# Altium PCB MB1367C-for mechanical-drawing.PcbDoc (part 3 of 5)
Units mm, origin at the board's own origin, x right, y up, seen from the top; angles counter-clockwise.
Board outline 70 x 82.5 mm, 4 copper layers (Top Layer, Signal Layer 1, Signal Layer 2, Bottom Layer), stack 1.614 mm thick; 191 components, 143 nets, 808 pads, 920 vias.
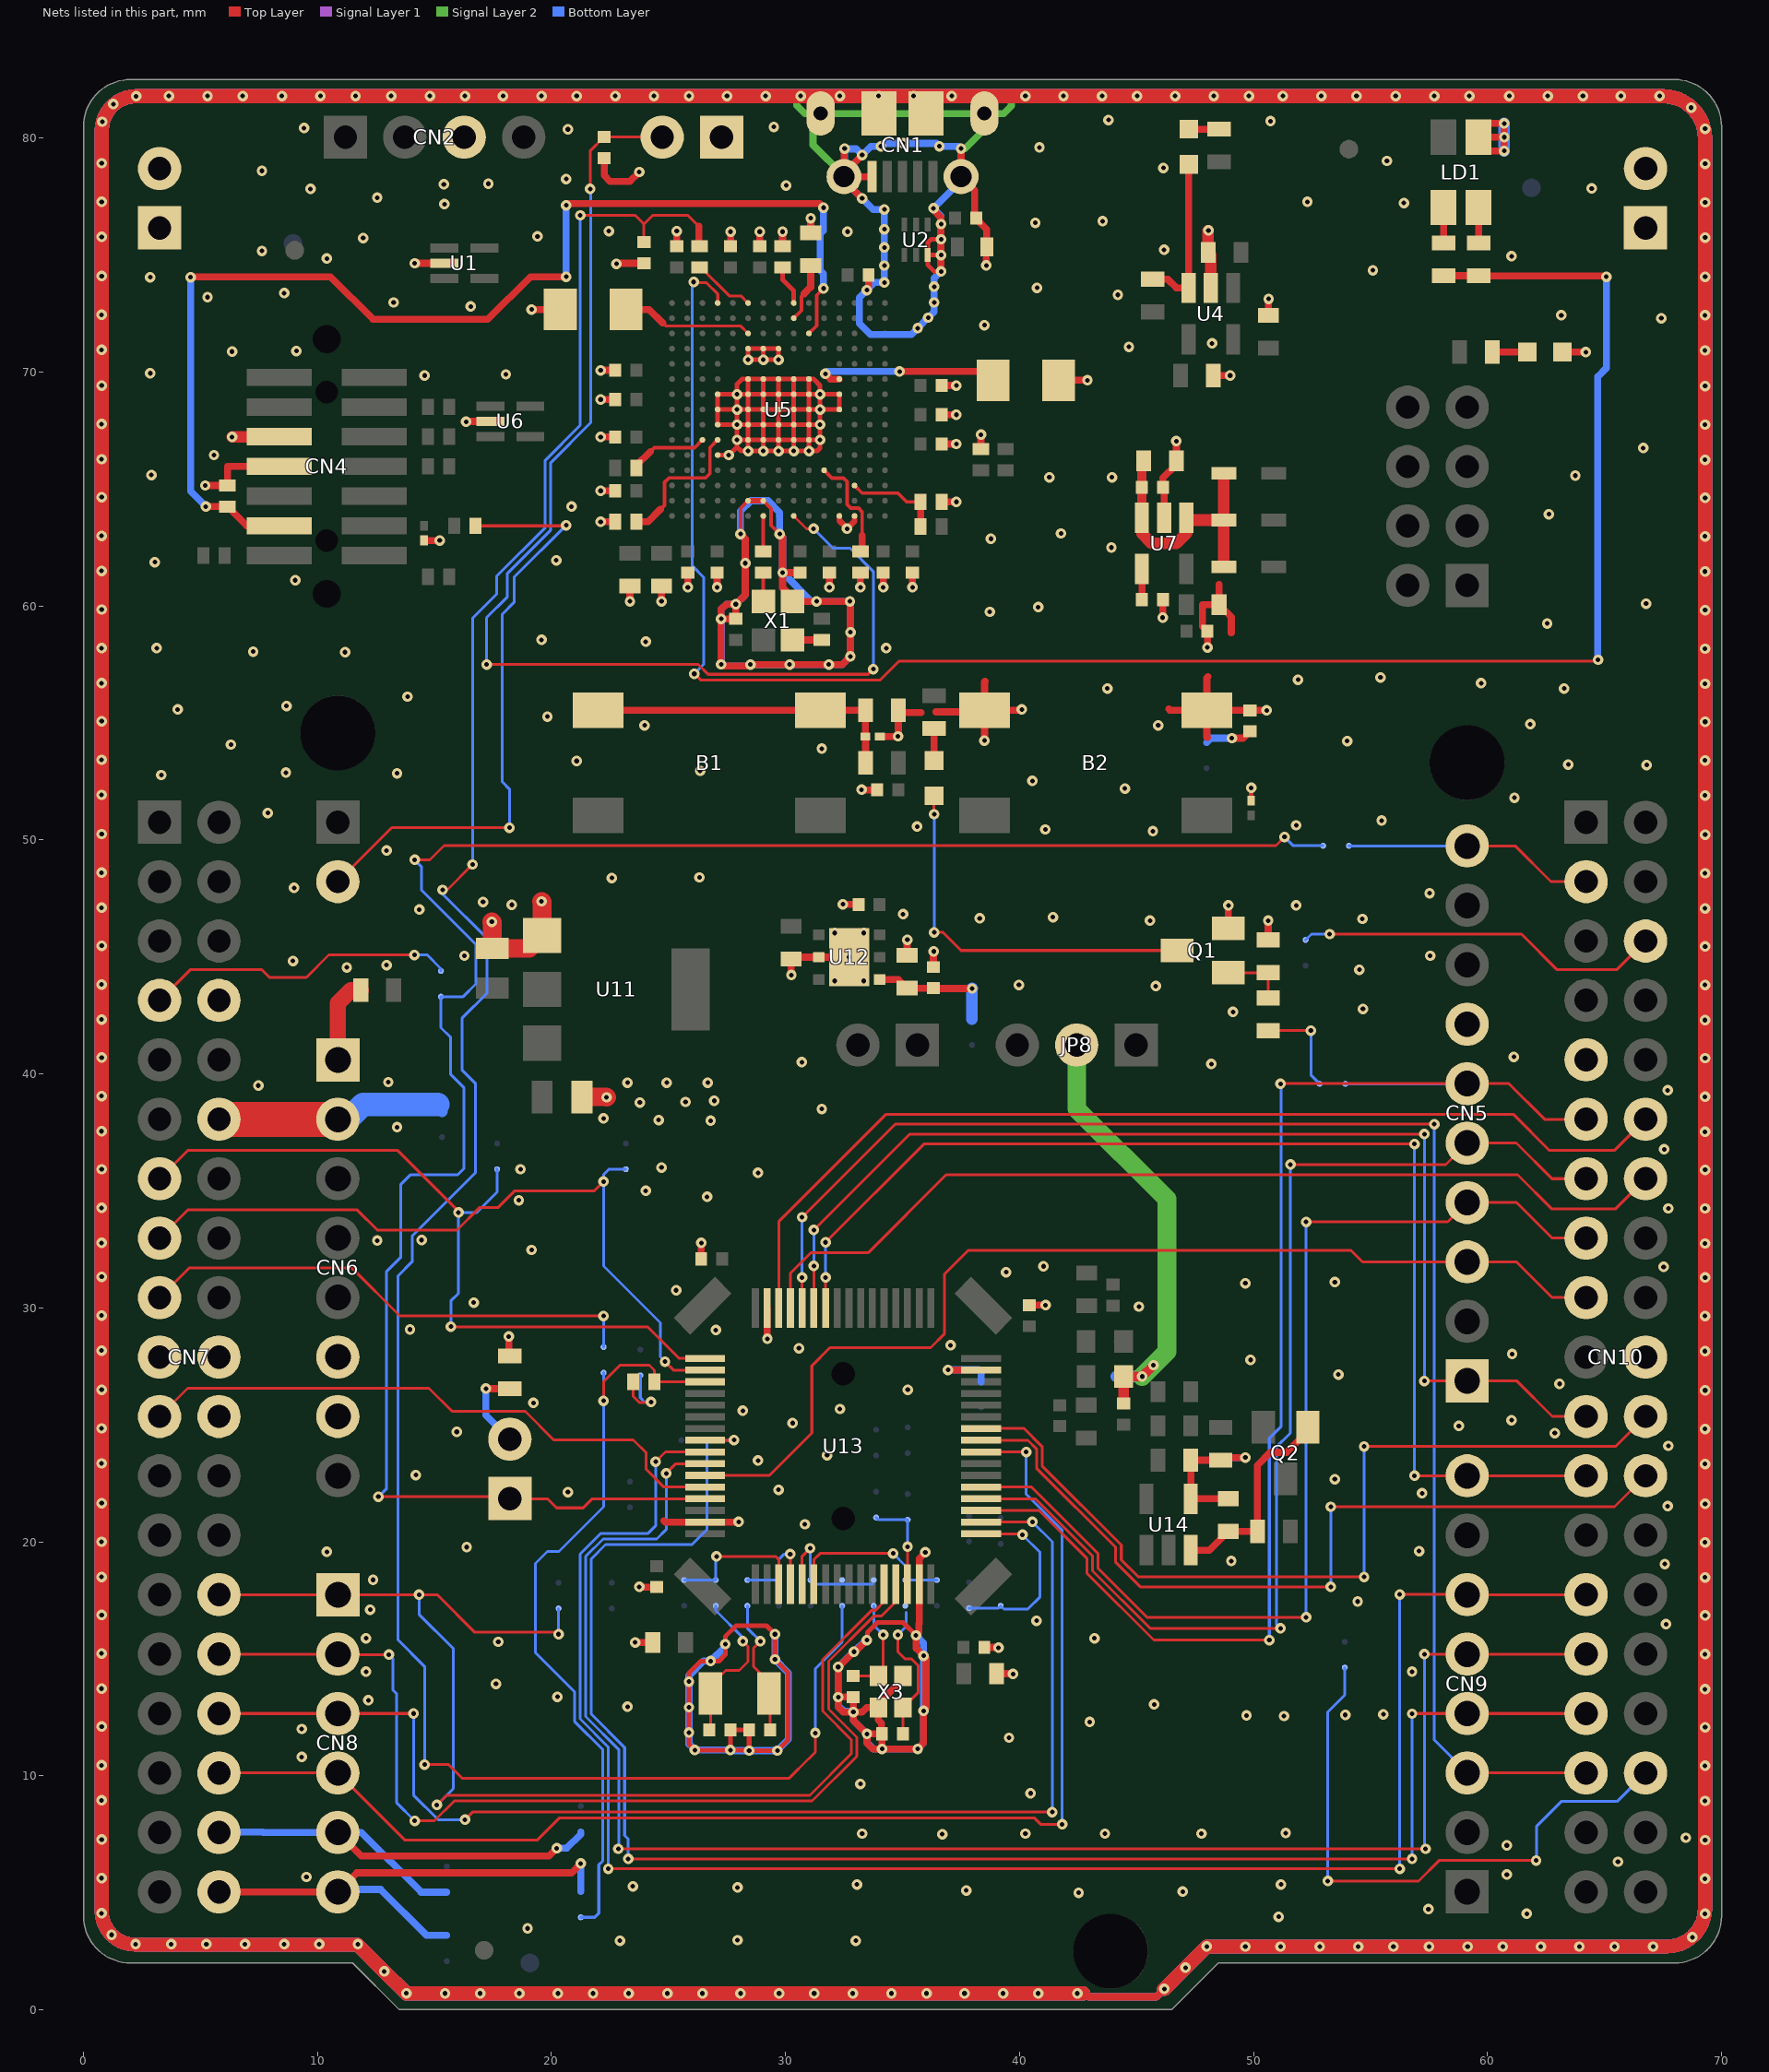
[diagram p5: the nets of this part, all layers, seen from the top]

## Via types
v1: diameter 0.45, hole 0.2, Top Layer to Bottom Layer, tented both sides, 920 vias

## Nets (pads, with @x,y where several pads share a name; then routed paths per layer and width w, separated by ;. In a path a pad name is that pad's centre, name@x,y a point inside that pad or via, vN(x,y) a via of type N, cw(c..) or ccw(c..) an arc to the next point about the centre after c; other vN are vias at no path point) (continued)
GND: B2.3 B2.4 C1.1 C2.1 C3.1 C4.1 C5.1 C6.1 C7.1 C8.1 C9.1 C10.1 C11.1 C12.1 C13.1 C14.1 C15.1 C16.1 C17.1 C18.1 C19.1 C20.1 C21.1 C22.1 C23.1 C24.1 C25.1 C26.1 C27.1 C28.1 C29.1 C30.1 C31.1 C32.1 C33.1 C34.1 C35.1 C36.1 C37.1 C38.1 C39.1 C40.1 C41.1 C42.1 C45.1 C52.1 C53.1 C54.1 C55.1 C56.1 C57.2 C58.2 C59.1 CN1.5 CN1.6 CN1.7 CN1.8 CN1.9 CN1.10 CN1.11 CN2.3 CN4.5 CN4.7 CN5.7 CN6.6 CN6.7 CN7.8 CN7.19 CN7.20 CN7.22 CN10.9 CN10.20 CN11.1 CN11.2 CN12.1 CN12.2 JP1.1 LD1.1 LD3.2 Q1.2 R5.1 R8.2 R11.1 R15.1 R16.2 R17.1 R21.1 R26.1 R28.1 R31.1 SB11.1 U1.2 U2.3 U3.2 U4.2 U5.D5 U5.D7 U5.D8 U5.D9 U5.F2 U5.F6 U5.F7 U5.F8 U5.F9 U5.F10 U5.F12 U5.G2 U5.G6 U5.G7 U5.G8 U5.G9 U5.G10 U5.G12 U5.H6 U5.H7 U5.H8 U5.H9 U5.H10 U5.H12 U5.J6 U5.J7 U5.J8 U5.J9 U5.J10 U5.K6 U5.K7 U5.K8 U5.K9 U5.K10 U5.M1 U5.M8 U5.M9 U5.N1 U6.2 U7.2 U8.2 U9.2 U10.2 U11.1 U12.2 U12.EP U13.15 U13.31 U13.47 U13.63 X1.2 X3.2 X3.4 | length 1507.3
  Top Layer w0.15: v1(28.075,63.075) 28.075,64.175 U5.F2@28.4,64.5 ; U5.G2@29.05,64.5 29.38,64.17 29.38,63.445 v1(29.75,63.075)
  Top Layer w0.2: U5.D5@27.1,66.45 v1(27.575,66.45) 27.925,66.8 ; v1(33.475,15.8) 33.5,15.825 33.5,16.125 33.93,16.555 35.02,16.555 v1(35.575,16) ; v1(36.65,74.3) 36.35,74.3 36.075,74.575 U2.3@36.075,75 ; v1@36.65,74.975 36.625,75 U2.3@36.075,75 ; v1(36.65,75.675) 36.225,75.675 36.075,75.525 U2.3@36.075,75 ; U10.2@49.895,51.677 49.895,52.22 v1(49.9,52.225) ; U5.D8@27.1,68.4 v1(27.925,68.4) ; U5.D8@27.1,68.4 U5.D7@27.1,67.75 v1(27.925,67.75) ; U5.D8@27.1,68.4 U5.D9@27.1,69.05 v1(27.925,69.05) ; v1(27.645,11.1) v1(26.125,11.1) 25.875,11.35 v1(25.875,11.85) v1(25.875,12.925) v1(25.875,14.025) 25.875,14.399 26.376,14.9 v1(26.8,14.9) 27.15,14.9 27.425,15.175 v1(27.425,15.625) 27.425,15.949 27.891,16.415 29.185,16.415 v1(29.55,16.05) v1(29.55,14.975) 30.105,14.42 30.105,11.53 v1(29.65,11.075) v1(28.445,11.075) ; v1(27.645,11.1) C57.2@27.645,11.965 C58.2@28.445,11.965 v1(28.445,11.075) ; v1(27.645,11.1) 28.42,11.1 v1(28.445,11.075) ; 27.925,66.8 v1(27.925,67.1) ; 27.925,66.8 28.1,66.625 v1(28.4,66.625) ; v1(27.925,67.1) U5.F6@28.4,67.1 ; v1(27.925,67.1) v1(27.925,67.75) ; v1(27.925,67.75) U5.F7@28.4,67.75 ; v1(27.925,67.75) v1(27.925,68.4) ; v1(27.925,68.4) U5.F8@28.4,68.4 ; v1(27.925,68.4) v1(27.925,69.05) ; v1(27.925,69.05) U5.F9@28.4,69.05 ; v1(27.925,69.05) 27.925,69.475 28.15,69.7 U5.F10@28.4,69.7 ; v1(28.4,66.625) U5.F6@28.4,67.1 ; v1(28.4,66.625) v1(29.05,66.625) ; U5.F6@28.4,67.1 U5.G6@29.05,67.1 ; U5.F6@28.4,67.1 U5.F7@28.4,67.75 ; U5.F7@28.4,67.75 U5.F8@28.4,68.4 ; U5.F7@28.4,67.75 U5.G7@29.05,67.75 ; U5.F8@28.4,68.4 U5.F9@28.4,69.05 ; U5.F8@28.4,68.4 U5.G8@29.05,68.4 ; U5.F9@28.4,69.05 U5.F10@28.4,69.7 ; U5.F9@28.4,69.05 U5.G9@29.05,69.05 ; U5.F10@28.4,69.7 U5.G10@29.05,69.7 ; v1(29.05,66.625) U5.G6@29.05,67.1 ; v1(29.05,66.625) v1(29.7,66.625) ; U5.G6@29.05,67.1 U5.H6@29.7,67.1 ; U5.G6@29.05,67.1 U5.G7@29.05,67.75 ; U5.G7@29.05,67.75 U5.G8@29.05,68.4 ; U5.G7@29.05,67.75 U5.H7@29.7,67.75 ; U5.G8@29.05,68.4 U5.G9@29.05,69.05 ; U5.G8@29.05,68.4 U5.H8@29.7,68.4 ; U5.G9@29.05,69.05 U5.G10@29.05,69.7 ; U5.G9@29.05,69.05 U5.H9@29.7,69.05 ; U5.G10@29.05,69.7 U5.H10@29.7,69.7 ; v1(29.05,70.525) U5.G12@29.05,71 ; v1(29.05,70.525) v1(29.7,70.525) U5.H12@29.7,71 U5.G12@29.05,71 ; v1(29.05,70.525) v1(28.4,70.525) U5.F12@28.4,71 U5.G12@29.05,71 ; v1(29.7,66.625) U5.H6@29.7,67.1 ; v1(29.7,66.625) v1(30.35,66.625) ; U5.H6@29.7,67.1 U5.J6@30.35,67.1 ; U5.H6@29.7,67.1 U5.H7@29.7,67.75 ; U5.H7@29.7,67.75 U5.H8@29.7,68.4 ; U5.H7@29.7,67.75 U5.J7@30.35,67.75 ; U5.H8@29.7,68.4 U5.H9@29.7,69.05 ; U5.H8@29.7,68.4 U5.J8@30.35,68.4 ; U5.H9@29.7,69.05 U5.H10@29.7,69.7 ; U5.H9@29.7,69.05 U5.J9@30.35,69.05 ; U5.H10@29.7,69.7 U5.J10@30.35,69.7 ; v1(30.35,66.625) U5.J6@30.35,67.1 ; v1(30.35,66.625) v1(31,66.625) ; U5.J6@30.35,67.1 U5.J7@30.35,67.75 ; U5.J6@30.35,67.1 U5.K6@31,67.1 ; U5.J7@30.35,67.75 U5.J8@30.35,68.4 ; U5.J7@30.35,67.75 U5.K7@31,67.75 ; U5.J8@30.35,68.4 U5.J9@30.35,69.05 ; U5.J8@30.35,68.4 U5.K8@31,68.4 ; U5.J9@30.35,69.05 U5.J10@30.35,69.7 ; U5.J9@30.35,69.05 U5.K9@31,69.05 ; U5.J10@30.35,69.7 U5.K10@31,69.7 ; v1(31,66.625) U5.K6@31,67.1 ; v1(31,66.625) 31.35,66.625 31.475,66.75 v1(31.475,67.1) ; U5.K6@31,67.1 v1(31.475,67.1) ; U5.K6@31,67.1 U5.K7@31,67.75 ; U5.K7@31,67.75 v1(31.475,67.75) ; U5.K7@31,67.75 U5.K8@31,68.4 ; U5.K8@31,68.4 U5.K9@31,69.05 ; U5.K8@31,68.4 v1(31.475,68.4) ; U5.K9@31,69.05 U5.K10@31,69.7 ; U5.K9@31,69.05 v1(31.475,69.05) ; U5.K10@31,69.7 31.2,69.7 31.475,69.425 v1(31.475,69.05) ; v1(31.475,67.1) v1(31.475,67.75) ; v1(31.475,67.75) v1(31.475,68.4) ; v1(31.475,68.4) U5.M8@32.3,68.4 U5.M9@32.3,69.05 v1(31.475,69.05) ; v1(31.475,68.4) v1(31.475,69.05)
  Top Layer w0.25: U5.F2@28.4,64.5 U5.G2@29.05,64.5 ; U5.M1@32.3,63.85 32.3,63.65 32.625,63.325 v1(32.625,63.3) 32.95,63.625 U5.N1@32.95,63.85
  Top Layer w0.3: v1(5.2,65.15) R15.1@6.15,65.15 6.15,65.965 CN4.7@8.363,65.965 ; v1(6.35,67.225) v1@6.36,67.235 ; 13.64,81.92 13.67,81.89 ; v1(14.15,74.65) U1.2@15.425,74.65 ; U8.2@14.545,62.802 15.222,62.802 v1(15.222,62.797) ; v1(16.35,67.875) 16.365,67.89 U6.2@17.395,67.89 ; v1(18.175,28.775) 18.175,27.99 R31.1@18.22,27.945 ; v1(19.15,72.675) C10.1@20.375,72.675 ; v1(22.1,63.6) R17.1@22.725,63.6 ; v1(22.1,64.925) C21.1@22.725,64.925 ; v1(22.1,67.225) C17.1@22.725,67.225 ; v1(22.1,68.825) C15.1@22.725,68.825 ; v1(22.1,70.075) C13.1@22.725,70.075 ; C1.1@22.25,79.15 22.25,78.4 22.5,78.15 23.35,78.15 v1(23.75,78.55) ; v1(22.775,74.625) 22.8,74.65 C3.1@23.95,74.65 ; v1(23.35,60.2) C28.1@23.35,60.85 ; v1(23.575,15.7) C53.1@24.325,15.7 ; v1(23.75,18.075) 23.76,18.065 C52.1@24.495,18.065 ; v1(24.7,60.2) C29.1@24.7,60.85 ; 24.8,20.9 24.86,20.84 27.99,20.84 v1(28,20.85) ; C6.1@25.35,75.375 v1(25.35,76.025) ; v1(25.825,60.8) C22.1@25.825,61.425 ; C42.1@26.395,32.09 26.395,32.77 v1(26.4,32.775) ; v1(27.075,60.8) C23.1@27.075,61.425 ; C7.1@27.65,75.375 v1(27.65,76) ; v1(28.075,63.075) 28.28,62.87 v1(28.28,61.83) 28.28,60.48 v1(27.875,60.075) ; C8.1@28.9,75.375 v1(28.9,76) ; U13.47@29.21,29.99 29.21,28.69 v1(29.225,28.675) ; v1(29.75,63.075) 29.875,62.95 v1(29.875,61.425) ; R5.1@29.875,75.375 v1(29.875,76) ; v1(30.25,44.225) 30.245,44.23 C37.1@30.245,44.915 30.32,44.99 U12.2@31.42,44.99 v1(32.72,44.99) ; C24.1@30.55,61.35 C24.1@30.625,61.425 v1(29.875,61.425) ; C4.1@31.075,75.95 v1(31.075,76.575) ; v1(31.875,60.8) C25.1@31.875,61.425 ; v1(32.45,47.25) 32.46,47.24 C36.1@33.12,47.24 ; v1(32.525,79.55) 32.5,79.525 CN1.7@32.5,78.5 ; v1(32.775,58.875) v1@32.77,58.88 ; v1(33.2,60.8) R21.1@33.2,61.425 ; v1(33.25,52.15) 33.26,52.14 C35.1@33.92,52.14 ; v1(33.275,77.425) 32.5,78.2 CN1.7@32.5,78.35 ; v1(33.275,79.275) CN1.7@32.5,78.5 ; v1(33.475,15.8) 32.975,15.3 v1(32.925,15.3) 32.275,14.65 v1(32.25,14.65) 32.255,14.645 v1(32.255,13.36) ; v1(33.475,73.5) 33.55,73.575 C9.1@33.55,74.15 ; CN1.5@33.7,78.35 CN1.7@32.5,78.35 ; U9.2@34.033,54.415 34.79,54.415 v1(34.805,54.43) 34.82,54.43 R26.1@34.82,55.54 34.91,55.45 35.8,55.45 ; v1(34.175,60.8) C26.1@34.175,61.425 ; X3.4@35.02,14.265 35.02,14.133 33.97,13.083 X3.2@33.97,12.915 ; C39.1@35.195,45.065 35.195,45.725 v1(35.205,45.735) ; v1(35.425,60.8) C27.1@35.425,61.425 ; v1@35.875,12.775 36.005,12.905 36.005,15.02 v1(35.9,15.125) 35.575,15.45 v1(35.575,16) 35.7,16.125 35.7,16.5 35.71,16.51 35.71,19.285 v1(35.975,19.55) ; v1(35.9,12.775) 35.9,11.4 v1(35.65,11.15) v1(34.125,11.15) ; C40.1@36.32,44.565 36.32,45.225 v1(36.33,45.235) ; v1(36.325,77) 36.325,76.925 36.65,76.6 v1(36.65,76.325) v1(36.65,75.675) v1(36.65,75) 36.65,74.975 v1(36.65,74.3) ; 36.425,55.475 38.43,55.475 B2.4@38.505,55.55 ; R16.2@36.675,64.45 v1(37.3,64.45) ; C18.1@36.675,66.925 v1(37.3,66.925) ; C16.1@36.675,68.175 v1(37.3,68.175) ; C14.1@36.675,69.425 v1(37.3,69.425) ; v1(36.945,27.35) 36.935,27.34 U13.31@38.36,27.34 ; v1(37.5,79.55) CN1.6@37.5,78.35 38.08,77.77 38.08,76.62 38.1,76.6 38.6,76.1 U3.2@38.6,75.35 ; R11.1@38.35,66.7 v1(38.35,67.325) ; C54.1@38.495,15.49 39.085,15.49 v1(39.1,15.475) ; v1(38.5,54.25) 38.505,54.255 B2.4@38.505,55.55 ; 38.525,56.775 38.505,56.755 B2.4@38.505,55.55 ; v1(38.58,74.555) 38.58,74.855 ; C55.1@39.02,14.365 39.715,14.365 39.725,14.375 v1(39.725,14.35) ; v1(40.1,55.575) 40.075,55.55 B2.4@38.505,55.55 ; C45.1@40.42,30.115 v1(41.115,30.115) ; C12.1@41.675,69.65 v1(42.9,69.65) ; 42.72,0.7 42.82,0.7 42.97,0.55 45.845,0.55 v1(46.185,0.89) ; v1(46.12,59.505) 46.13,59.505 C30.1@46.13,60.275 C30.1@46.18,60.325 ; U7.2@46.18,63.775 46.18,65.025 C20.1@46.13,65.075 46.13,65.48 46.705,66.055 C19.1@46.705,66.2 46.705,67.045 v1(46.7,67.05) ; 46.375,55.6 46.425,55.55 B2.3@48.005,55.55 ; 48.025,54.375 48.005,54.395 B2.3@48.005,55.55 ; v1(48.03,58.23) C33.1@48.03,58.925 47.825,59.13 47.825,60.05 C31.1@48.53,60.05 ; 48.05,56.975 48.005,56.93 B2.3@48.005,55.55 ; C5.1@48.06,75.12 C5.1@48.175,75.005 ; v1@48.06,76.035 v1(48.075,76.05) ; R8.2@48.285,69.845 48.995,69.845 v1(49,69.85) ; 48.525,60.925 48.53,60.92 C31.1@48.53,60.05 ; Q1.2@48.925,46.225 48.925,47.175 48.9,47.2 v1(48.925,47.2) ; 49.05,58.85 49.05,59.53 C31.1@48.53,60.05 ; v1(50.565,55.54) C34.1@49.845,55.54 49.835,55.55 B2.3@48.005,55.55 ; R28.1@50.625,45.725 v1(50.625,46.55) ; C11.1@50.635,72.42 50.635,73.135 v1(50.645,73.125) ; LD1.1@59.62,80.04 v1@60.71,80.04 ; LD1.1@59.65,79.45 v1(60.71,79.45) v1@60.71,80.04 ; LD1.1@59.65,80.625 v1(60.71,80.625) v1@60.71,80.04 ; v1(60.715,80.04) v1@60.71,80.04 ; LD3.2@63.2,70.85 v1(64.2,70.85) ; v1(27.25,59.45) 27.25,57.504 v1(27.251,57.503) 27.324,57.43 28.405,57.43 28.475,57.5 v1(28.5,57.5) v1(30.175,57.5) v1(31.85,57.5) 32.425,57.5 v1(32.77,57.845) v1@32.77,58.88 ; v1(27.25,59.45) 27.25,59.85 27.475,60.075 v1(27.875,60.075) ; v1(27.25,59.45) C32.1@27.875,59.45 v1(27.875,60.075) ; v1(29.875,61.425) 29.875,60.775 30.3,60.35 X1.2@30.3,60.2 v1(31.325,60.2) v1(32.75,60.2) 32.77,60.18 v1@32.77,58.88 ; v1(32.255,13.36) 32.26,13.365 C56.1@32.895,13.365 v1@32.895,12.73 ; v1(32.255,13.36) 32.255,12.945 32.475,12.725 v1@32.895,12.725 ; CN1.7@32.5,78.35 CN1.7@32.5,78.5 ; v1@32.895,12.725 v1(32.9,12.725) ; v1@32.895,12.725 32.895,12.37 v1(33.48,11.785) ; v1@32.895,12.725 v1@32.895,12.73 ; v1@32.895,12.73 v1(32.9,12.725) ; v1(32.9,12.725) 33.275,12.725 33.465,12.915 X3.2@33.97,12.915 ; v1(33.48,11.785) 33.485,11.79 C59.1@34.12,11.79 ; v1(33.48,11.785) 33.48,11.395 33.725,11.15 v1(34.125,11.15) ; X3.2@33.97,12.915 33.97,12.38 34.1,12.25 34.1,11.81 C59.1@34.12,11.79 ; C59.1@34.12,11.79 34.12,11.155 v1(34.125,11.15)
  Top Layer w0.5: v1@6.36,67.235 CN4.5@8.363,67.235 ; C5.1@48.06,75.12 v1@48.06,76.035 ; U4.2@48.175,73.595 C5.1@48.175,75.005
  Top Layer w0.6: 42.72,0.7 13.79,0.7 v1(12.85,1.64) 11.713,2.777 2.22,2.777 cw(c2.22,4.22) 0.777,4.22 v1(0.777,78.925) 0.777,80.315 cw(c2.252,80.315) v1(2.252,81.79) 13.67,81.79 67.502,81.79 cw(c67.502,79.997) 69.295,79.997 69.295,4.34 cw(c67.655,4.34) 67.655,2.7 47.995,2.7 v1(47.09,1.795) v1(46.185,0.89)
  Top Layer w0.8: v1(17.45,46.5) 17.47,46.48 C38.1@17.47,45.365 19.045,45.365 U11.1@19.595,45.915 19.595,47.355 v1(19.575,47.375) ; C41.1@21.295,39.015 22.335,39.015 v1(22.35,39)
  Signal Layer 1 w0.3: 13.64,81.92 13.67,81.89 ; 42.72,0.7 42.82,0.7 42.97,0.55 45.845,0.55 v1(46.185,0.89)
  Signal Layer 1 w0.6: 13.67,81.8 13.67,81.79 ; 42.72,0.7 13.79,0.7 v1(12.85,1.64) 11.713,2.777 2.22,2.777 cw(c2.22,4.22) 0.777,4.22 v1(0.777,78.925) 0.777,80.315 cw(c2.252,80.315) v1(2.252,81.79) 13.67,81.79 ; v1(46.185,0.89) v1(47.09,1.795) 47.995,2.7 67.655,2.7 ccw(c67.655,4.34) 69.295,4.34 69.295,79.997 ccw(c67.502,79.997) 67.502,81.79 13.67,81.79
  Signal Layer 2 w0.3: v1(27.251,57.503) v1(27.251,57.503) ; v1(28.5,57.5) v1(30.175,57.5) ; v1@30.475,81.79 30.475,81.4 30.825,81.05 CN1.8@31.5,81.05 ; CN1.7@32.5,78.35 32.5,78.375 31.175,79.7 31.175,80.725 CN1.8@31.5,81.05 ; v1(37.5,79.55) 37.675,79.55 38.5,80.375 CN1.9@38.5,81.05 ; 39.65,81.79 39.65,81.375 39.325,81.05 CN1.9@38.5,81.05 ; 42.72,0.7 42.82,0.7 42.97,0.55 45.845,0.55 v1(46.185,0.89) ; CN1.8@31.5,81.05 CN1.9@38.5,81.05
  Signal Layer 2 w0.6: 42.72,0.7 13.79,0.7 v1(12.85,1.64) 11.713,2.777 2.22,2.777 cw(c2.22,4.22) 0.777,4.22 v1(0.777,78.925) 0.777,80.315 cw(c2.252,80.315) v1(2.252,81.79) 13.67,81.79 30.475,81.79 39.65,81.79 67.502,81.79 cw(c67.502,79.997) 69.295,79.997 69.295,4.34 cw(c67.655,4.34) 67.655,2.7 47.995,2.7 v1(47.09,1.795) v1(46.185,0.89)
  Bottom Layer w0.3: 13.64,81.92 13.67,81.89 ; v1(27.425,15.625) 27.425,15.525 v1(26.8,14.9) 26.5,14.9 25.875,14.275 v1(25.875,14.025) v1(25.875,12.925) v1(25.875,11.85) 25.875,11.35 v1(26.125,11.1) v1(27.645,11.1) 27.67,11.075 v1(28.445,11.075) v1(29.65,11.075) 30.125,11.55 30.125,14.4 v1(29.55,14.975) v1(29.55,16.05) ; v1@28.05,63.075 28.28,62.845 v1(28.28,61.83) 28.28,60.48 v1(27.875,60.075) 27.475,60.075 27.25,59.85 v1(27.25,59.45) 27.251,59.449 v1(27.251,57.503) 27.324,57.43 28.43,57.43 v1(28.5,57.5) v1(30.175,57.5) v1(31.85,57.5) 32.425,57.5 v1(32.77,57.845) 32.775,57.85 v1(32.775,58.875) 32.775,60.175 v1(32.75,60.2) v1(31.325,60.2) 31.1,60.2 v1(29.875,61.425) 29.875,62.95 v1(29.75,63.075) 29.75,64 29.25,64.5 28.525,64.5 28.075,64.05 v1(28.075,63.075) ; v1@32.513,79.538 v1@32.525,79.538 ; v1(32.525,79.55) v1@32.525,79.538 ; v1(33.475,15.8) 33.425,15.8 v1(32.925,15.3) 32.9,15.3 v1(32.25,14.65) 32.255,14.645 v1(32.255,13.36) 32.255,12.995 32.5,12.75 32.875,12.75 v1(32.9,12.725) 32.9,12.365 v1(33.48,11.785) 33.48,11.445 33.775,11.15 v1(34.125,11.15) v1(35.65,11.15) 35.9,11.4 v1(35.9,12.775) v1(35.9,15.125) 35.9,15.675 v1(35.575,16) ; v1(36.945,27.35) 38.25,27.35 38.36,27.24 SB11.1@38.36,26.84 ; 42.72,0.7 42.82,0.7 42.97,0.55 45.845,0.55 v1(46.185,0.89) ; v1@32.525,79.538 32.525,78.375 CN1.7@32.5,78.35 32.5,78.2 v1(33.275,77.425) 33.75,76.95 v1(34.225,76.95) v1(34.225,76.1) v1(34.225,75.325) v1(34.225,74.55) v1(34.225,73.825) 33.8,73.825 v1(33.475,73.5) 33.15,73.175 33.15,72.075 33.625,71.6 35.375,71.6 v1(35.65,71.875) v1(36.1,72.325) 36.35,72.575 v1(36.35,72.975) v1(36.35,73.65) 36.35,74 v1(36.65,74.3) v1(36.65,75) v1(36.65,75.675) v1(36.65,76.325) 36.65,76.675 v1(36.325,77) 37.5,78.175 CN1.6@37.5,78.35 v1(37.5,79.55) 37.4,79.65 v1(36.575,79.65) 36.45,79.775 v1(35.025,79.775) 34.2,79.775 v1(34.075,79.65) 33.65,79.65 v1(33.275,79.275) 33.012,79.538 v1@32.525,79.538
  Bottom Layer w0.5: v1(60.71,79.45) v1(60.71,80.625)
  Bottom Layer w0.6: 42.72,0.7 13.79,0.7 v1(12.85,1.64) 11.713,2.777 2.22,2.777 cw(c2.22,4.22) 0.777,4.22 v1(0.777,78.925) 0.777,80.315 cw(c2.252,80.315) v1(2.252,81.79) 13.67,81.79 67.502,81.79 cw(c67.502,79.997) 69.295,79.997 69.295,4.34 cw(c67.655,4.34) 67.655,2.7 47.995,2.7 v1(47.09,1.795) v1(46.185,0.89)
  other v1: 13.8,0.7 15.45,0.698 16.95,0.698 18.625,0.698 20.275,0.696 21.775,0.696 23.3,0.698 24.95,0.696 26.45,0.696 28.075,0.698 29.725,0.696 31.225,0.696 32.875,0.698 34.525,0.696 36.025,0.696 37.65,0.698 39.3,0.696 40.8,0.696 42.475,0.698 48,2.7 49.65,2.698 51.15,2.698 52.825,2.698 54.475,2.696 55.975,2.696 57.5,2.698 59.15,2.696 60.65,2.696 62.275,2.698 63.925,2.696 65.425,2.696 67.075,2.698 2.225,2.802 3.75,2.804 5.25,2.804 6.9,2.802 8.575,2.802 10.075,2.802 11.725,2.8 22.925,2.95 33,2.95 27.95,2.975 68.75,3.1 1.2,3.2 18.975,3.475 51.075,3.975 61.675,4.1 69.296,4.1 0.773,4.125 57.475,4.3 42.525,5 46.975,5.05 37.725,5.1 27.95,5.225 23.475,5.275 33.05,5.35 51.175,5.35 69.296,5.6 0.773,5.625 9.525,5.675 60.825,5.775 65.575,6.325 60.825,7.025 69.298,7.25 0.775,7.275 68.475,7.35 36.7,7.5 33.275,7.525 40.25,7.525 43.65,7.525 47.775,7.525 51.375,7.55 69.296,8.925 0.773,8.95 40.475,9.25 33.2,9.65 69.296,10.425 0.773,10.45 9.325,10.8 39.55,11.625 9.325,12 69.298,12.075 0.775,12.1 43,12.3 51.3,12.55 49.7,12.575 53.925,12.6 55.55,12.625 23.25,12.95 45.75,13.05 12.175,13.225 20.25,13.375 69.296,13.7 0.773,13.725 17.625,13.925 12.075,14.45 56.775,14.45 69.296,15.2 0.773,15.225 17.725,15.725 12.075,15.875 43.2,15.875 67.625,16.475 40.725,16.625 69.298,16.85 0.775,16.875 12.25,17.1 54.45,17.45 12.375,18.375 69.296,18.475 0.773,18.5 67.575,19.05 49.05,19.175 10.4,19.575 57.075,19.6 16.375,19.775 69.296,19.975 0.773,20 30.825,20.75 67.7,21.525 69.298,21.625 0.775,21.65 57.2,22.075 20.7,22.125 29.7,22.225 53.475,22.675 14.2,22.85 69.296,23.325 0.773,23.35 28.825,23.475 31.775,23.7 67.725,24.1 62.875,24.65 15.95,24.7 69.296,24.825 0.773,24.85 58.775,24.95 30.3,25.075 61.025,25.2 28.175,25.6 32.325,25.675 19.225,25.94 69.298,26.475 0.775,26.5 35.225,26.5 63.075,26.75 53.625,27.15 49.875,27.775 61.05,28.025 69.296,28.15 0.773,28.175 30.575,28.275 37.05,28.4 27.025,29.05 13.95,29.075 69.296,29.65 0.773,29.675 45.1,30.05 16.675,30.225 25.325,30.75 49.65,31.05 53.475,31.1 69.298,31.3 0.775,31.325 39.425,31.525 67.525,31.75 41.025,31.775 19.15,32.475 69.296,32.75 0.773,32.775 12.55,32.875 14.45,32.9 67.725,34.25 69.296,34.25 0.773,34.275 18.6,34.6 26.65,34.75 24.025,35 28.825,35.775 69.298,35.9 0.775,35.925 18.675,35.925 24.7,36 67.55,36.775 69.296,37.525 0.773,37.55 13.4,37.725 26.8,38 24.575,38.025 22.225,38.1 31.55,38.5 23.775,38.775 25.725,38.8 26.95,38.85 69.296,39.025 0.773,39.05 67.7,39.3 7.475,39.5 23.25,39.625 24.925,39.625 26.675,39.625 13.025,39.65 48.2,40.425 30.7,40.5 69.298,40.675 0.775,40.7 61.125,40.725 69.296,42.3 0.773,42.325 49.125,42.65 54.675,42.775 45.825,43.75 39.975,43.8 69.296,43.8 0.773,43.825 32.1,43.975 33.35,43.975 54.525,44.45 11.25,44.55 12.95,44.65 8.95,44.825 16.275,45.05 57.55,45.05 69.298,45.45 0.775,45.475 32.1,46.025 33.35,46.025 45.575,46.55 54.65,46.625 38.3,46.65 41.425,46.7 35.025,46.825 14.35,47.025 69.296,47.075 0.773,47.1 51.825,47.2 18.3,47.225 17.075,47.35 57.525,47.725 9,47.95 22.575,48.375 26.325,48.4 69.296,48.575 0.773,48.6 12.95,49.55 69.298,50.225 0.775,50.25 45.7,50.375 41.1,50.45 35.625,50.575 51.825,50.625 55.475,50.825 7.875,51.15 61.15,51.8 69.296,51.9 0.773,51.925 44.5,52.2 40.55,52.525 3.325,52.775 13.4,52.85 8.65,52.875 26.35,52.95 66.8,53.2 63.45,53.225 21.075,53.375 69.296,53.4 0.773,53.425 31.55,53.9 6.3,54.075 54,54.225 23.975,54.9 45.925,54.9 61.825,54.95 69.298,55.05 0.775,55.075 19.825,55.275 4.025,55.575 8.675,55.725 13.85,56.125 43.75,56.475 63.275,56.475 69.296,56.675 0.773,56.7 59.725,56.7 51.9,56.85 55.425,56.95 11.175,58.025 7.25,58.05 69.296,58.175 0.773,58.2 3.125,58.2 34.3,58.2 24.025,58.475 19.575,58.55 62.55,59.25 38.725,59.75 69.298,59.825 0.775,59.85 40.8,59.95 66.775,60.1 9.05,61.1 69.296,61.475 0.773,61.5 3.05,61.875 20.2,61.95 43.925,62.5 38.775,62.875 69.296,62.975 0.773,63 41.775,63.1 62.625,63.925 20.85,64.25 69.298,64.625 0.775,64.65 41.275,65.5 43.95,65.5 63.75,65.575 2.9,65.6 69.296,66.25 0.773,66.275 5.575,66.45 66.65,66.75 69.296,67.75 0.773,67.775 69.298,69.4 0.775,69.425 14.575,69.85 18.05,69.9 2.85,69.95 6.35,70.875 9.1,70.9 69.296,70.925 0.773,70.95 44.675,71.075 48.225,71.225 38.5,72 67.425,72.3 63.15,72.425 69.296,72.425 0.773,72.45 16.55,72.8 13.25,72.975 5.3,73.2 44.2,73.3 8.575,73.375 40.75,73.6 2.85,74.05 69.298,74.075 0.775,74.1 55.1,74.35 10.4,74.85 61.025,74.95 7.625,75.175 46.175,75.225 11.95,75.725 69.298,75.75 0.775,75.775 19.4,75.8 32.65,76 22.45,76.025 40.675,76.375 43.55,76.45 15.425,77.175 56.425,77.225 69.298,77.25 0.775,77.275 52.3,77.275 12.55,77.45 9.7,77.825 64.45,77.85 30.025,77.975 15.4,78.025 17.3,78.05 20.625,78.25 7.625,78.6 46.15,78.725 69.3,78.9 55.7,79.025 40.85,79.6 20.7,80.375 69.3,80.4 9.425,80.425 29.5,80.475 0.8,80.7 50.725,80.725 43.8,80.775 68.7,81.3 1.275,81.45 3.65,81.8 5.3,81.798 6.8,81.798 8.475,81.798 10.125,81.796 11.625,81.796 13.15,81.798 14.8,81.796 16.3,81.796 17.925,81.798 19.575,81.796 21.075,81.796 22.725,81.798 24.375,81.796 25.875,81.796 27.5,81.798 29.15,81.796 30.65,81.796 32.325,81.798 33.975,81.796 35.475,81.796 37.1,81.798 40.25,81.796 41.875,81.798 43.525,81.796 45.025,81.796 46.65,81.798 48.3,81.796 49.8,81.796 51.25,81.798 52.9,81.796 54.4,81.796 56.075,81.798 57.725,81.796 59.225,81.796 60.925,81.798 62.575,81.796 64.075,81.796 65.7,81.798 67.35,81.796
GNDDetect: CN4.11 R15.2 U5.K13 | length 51
  Top Layer w0.15: U5.K13@31,71.65 31.33,71.98 31.33,73.28 v1(31.625,73.575)
  Top Layer w0.3: v1(4.575,74.05) 4.6,74.075 10.55,74.075 12.375,72.25 17.275,72.25 19.1,74.075 v1(20.625,74.075) ; v1(5.225,64.25) R15.2@6.15,64.25 6.975,63.425 CN4.11@8.363,63.425 ; v1(20.625,77.125) 20.695,77.195 31.455,77.195 v1(31.625,77.025)
  Bottom Layer w0.3: v1(4.575,74.05) 4.575,64.9 v1(5.225,64.25) ; v1(20.625,74.075) v1(20.625,77.125) ; v1(31.625,73.575) 31.625,74.2 31.475,74.35 31.475,75.9 31.625,76.05 v1(31.625,77.025)
IOREF: CN6.2 CN7.12 SB39.2 | length 20.2
  Top Layer w1.5: CN7.12@5.79,38.06 CN6.2@10.87,38.06
  Signal Layer 2 w1.5: CN7.12@5.79,38.06 CN6.2@10.87,38.06
  Bottom Layer w0.5: 15.15,38.7 15.325,38.525 SB39.2@15.325,38.4
  Bottom Layer w1: CN6.2@10.87,38.06 11.31,38.06 11.95,38.7 15.15,38.7
  Bottom Layer w1.5: CN7.12@5.79,38.06 CN6.2@10.87,38.06
LED_STLK: R2.2 R3.2 U5.D15 | length 83
  Top Layer w0.12: v1@26.075,73.825 26.617,73.825 27.105,73.337 27.105,72.955 U5.D15@27.1,72.95 ; v1(26.1,57.1) 26.115,57.1 26.375,56.84 34.051,56.84 34.851,57.64 64.665,57.64 v1(64.725,57.7) ; R2.2@58.12,74.115 R2.2@58.135,74.1 ; v1(65.075,74.075) 65.075,74.1 65.075,74.125 v1@65.1,74.1
  Top Layer w0.3: R2.2@58.12,74.115 R3.2@59.62,74.115 ; R2.2@58.135,74.1 65.075,74.1 v1@65.1,74.1
  Bottom Layer w0.12: v1(26.075,73.85) 26.02,73.795 26.02,61.707 26.5,61.227 26.5,57.5 v1(26.1,57.1) ; v1@64.7,57.725 v1(64.725,57.7)
  Bottom Layer w0.3: v1@64.7,57.725 64.7,69.8 65.075,70.175 v1(65.075,74.075)
MCO: C3.2 R4.2 SB27.1 | length 103.5
  Top Layer w0.12: v1(14.575,10.475) 15.607,10.475 16.197,9.885 30.146,9.885 31.001,10.741 31.009,10.741 31.275,11.007 v1(31.275,11.825) ; v1(15.346,47.868) 15.543,47.868 v1(16.625,48.95) ; v1(21.225,76.7) 23.575,76.7 23.95,76.325 ; C3.2@23.95,75.55 23.95,76.325 ; 26.3,76.225 25.825,76.7 24.325,76.7 23.95,76.325
  Top Layer w0.3: 26.3,76.225 26.3,75.4 R4.2@26.325,75.375
  Bottom Layer w0.12: v1(14.575,10.475) 14.575,14.675 13.43,15.82 13.43,31.355 14.045,31.97 14.045,33.068 16.745,35.768 16.745,39.6 16.17,40.175 16.17,42.376 17.25,43.456 17.25,45.788 15.346,47.692 v1(15.346,47.868) ; v1(16.625,48.95) 16.625,59.475 17.65,60.5 17.65,61.271 19.73,63.351 19.73,66.23 21.225,67.725 v1(21.225,76.7) ; v1(31.275,11.825) 31.275,14.575 32.42,15.72 SB27.1@32.42,17.265
NetB1_3: B1.3 B1.4 R26.2 R27.1 U9.1 | length 13.7
  Top Layer w0.3: B1.4@21.995,55.55 B1.3@31.495,55.55 33.41,55.55 33.408,55.548 U9.1@33.408,54.415 33.42,54.402 R27.1@33.42,53.29
NetC1_2: C1.2 JP1.2 U5.J1 | length 52.5
  Top Layer w0.12: v1(17.225,57.5) 17.23,57.505 26.268,57.505 26.693,57.08 33.53,57.08 v1(33.75,57.3) ; v1(21.65,77.825) 21.65,79.45 C1.2@22.25,80.05 ; C1.2@22.25,80.075 22.285,80.04 JP1.2@24.73,80.04 ; U5.J1@30.35,63.85 30.9,63.3 v1(31.2,63.3)
  Bottom Layer w0.12: v1(17.225,57.5) 17.225,59.5 18.1,60.375 18.1,61.382 19.97,63.252 19.97,66.131 21.67,67.831 21.67,77.805 v1(21.65,77.825) ; v1(31.2,63.3) 32.025,62.475 32.75,62.475 33.75,61.475 v1(33.75,57.3)
NetC4_2: C4.2 U5.J14 | length 2.6
  Top Layer w0.15: U5.J14@30.35,72.3 30.68,72.63 30.68,73.23 30.8,73.35
  Top Layer w0.3: 30.8,73.35 31.075,73.625 C4.2@31.075,74.55
NetC10_2: C10.2 U5.F13 | length 5.6
  Top Layer w0.12: 24.75,72.1 24.875,71.975 28.075,71.975 U5.F13@28.4,71.65
  Top Layer w0.3: C10.2@23.175,72.675 24.175,72.675 24.75,72.1
NetC12_2: C12.2 U5.M10 | length 8.1
  Top Layer w0.3: v1(31.7,69.925) 31.925,69.7 U5.M10@32.295,69.7 ; v1(34.875,70.025) 38.5,70.025 C12.2@38.875,69.65
  Bottom Layer w0.3: v1(31.7,69.925) 31.8,70.025 v1(34.875,70.025)
NetC19_2: C19.2 C20.2 D1.2 D2.2 D3.2 U7.1 U7.3 | length 11.7
  Top Layer w0.3: C19.2@45.23,66.125 C19.2@45.305,66.2 ; U7.1@47.13,63.775 47.15,63.755 U7.1@47.23,63.675
  Top Layer w0.4: U7.3@45.23,63.775 C20.2@45.23,65.075 C19.2@45.23,66.125
  Top Layer w0.5: U7.3@45.23,63.775 45.23,63.095 45.65,62.675 46.7,62.675 47.15,63.125 47.15,63.755 U7.1@47.15,63.8 ; U7.1@47.23,63.675 D2.2@48.73,63.675 ; D3.2@48.73,61.675 D2.2@48.73,63.675 ; D1.2@48.73,65.675 D2.2@48.73,63.675
NetC30_2: C30.2 U7.4 | length 1.3
  Top Layer w0.3: C30.2@45.23,60.275 U7.4@45.23,61.575
NetC34_2: C34.2 SB1.1 | length 2
  Top Layer w0.3: v1(49.075,54.35) 49.555,54.35 C34.2@49.845,54.64
  Bottom Layer w0.3: SB1.1@47.995,54.165 48.18,54.35 v1(49.075,54.35)
NetC39_2: C39.2 C40.2 SB5.1 U12.4 | length 5.4
  Top Layer w0.3: U12.4@34.02,44.04 34.82,44.04 C39.2@35.195,43.665 C40.2@36.32,43.665 36.335,43.65 v1(37.975,43.65)
  Bottom Layer w0.5: SB5.1@37.97,42.34 37.97,43.645 v1(37.975,43.65)
NetC47_2: C47.2 JP8.2 L2.1 SB10.1 | length 20.6
  Top Layer w0.4: L2.1@44.445,27.065 v1(45.24,27.065) v1(45.725,27.55)
  Top Layer w0.45: C47.2@44.445,25.915 L2.1@44.445,27.065
  Signal Layer 2 w0.8: JP8.2@42.445,41.235 42.445,38.505 46.3,34.65 46.3,28.125 v1(45.725,27.55) v1(45.24,27.065)
  Bottom Layer w0.5: SB10.1@44.145,27.065 v1(45.24,27.065) v1(45.725,27.55)
NetC51_1: C51.1 Q2.1 R35.1 U14.3 | length 8.9
  Top Layer w0.3: U14.3@47.32,19.64 48.12,19.64 C51.1@48.92,20.44 R35.1@50.17,20.44 50.17,23.27 50.725,23.825 51.425,23.825 52.32,24.72 Q2.1@52.32,24.89
NetC51_2: C51.2 R33.1 R34.2 SB14.2 U14.4 | length 6.7
  Top Layer w0.3: C51.2@48.92,21.84 U14.4@47.32,21.84 R34.2@47.32,23.49 R33.1@48.595,23.49 48.705,23.6 v1(49.65,23.6)
  Bottom Layer w0.3: SB14.2@48.595,23.59 49.64,23.59 v1(49.65,23.6)
NetCN5_10: CN5.10 CN10.3 SB2.1 | length 10.8
  Top Layer w0.12: CN5.10@59.13,49.744 61.181,49.744 62.705,48.22 CN10.3@64.21,48.22
  Bottom Layer w0.12: SB2.1@54.075,49.75 54.085,49.74 59.126,49.74 CN5.10@59.13,49.744
NetCN6_1: CN6.1 R30.1 | length 3.7
  Top Layer w0.12: CN6.1@10.87,40.6 CN6.1@10.885,40.615
  Top Layer w0.7: CN6.1@10.87,40.6 10.87,43.02 11.425,43.575 R30.1@11.85,43.575
NetCN7_7: CN7.7 SB4.2 | length 13.4
  Top Layer w0.12: CN7.7@3.25,43.14 4.56,44.45 7.625,44.45 7.95,44.125 9.525,44.125 10.484,45.084 v1(14.141,45.084)
  Bottom Layer w0.12: v1(14.141,45.084) 14.691,45.084 15.275,44.5 SB4.2@15.275,44.4
NetCN7_17: CN7.17 SB7.2 | length 21.7
  Top Layer w0.12: CN7.17@3.25,30.44 4.51,31.7 11.475,31.7 13.52,29.655 22.22,29.655 v1(22.225,29.65)
  Bottom Layer w0.12: SB7.2@22.225,28.325 v1(22.225,29.65)
NetCN7_36: CN7.36 CN8.5 SB34.1 SB35.2 | length 22.1
  Top Layer w0.3: CN8.5@10.87,7.58 11.875,6.575 19.9,6.575 v1(20.225,6.9)
  Bottom Layer w0.3: CN7.36@5.79,7.58 5.8,7.59 7.67,7.59 7.68,7.58 CN8.5@10.87,7.58 11.87,7.58 14.425,5.025 SB34.1@15.525,5.025 ; v1(20.225,6.9) 20.65,6.9 21.25,7.5 SB35.2@21.25,7.6
NetCN7_38: CN7.38 CN8.6 SB36.2 SB37.1 | length 22.7
  Top Layer w0.3: CN7.38@5.79,5.04 CN8.6@10.87,5.04 11.68,5.85 20.85,5.85 v1(21.25,6.25)
  Bottom Layer w0.3: CN8.6@10.87,5.04 10.97,5.14 12.695,5.14 14.66,3.175 SB36.2@15.525,3.175 ; SB37.1@21.25,5.05 v1(21.25,6.25)
NetCN10_6: CN10.6 SB3.1 | length 15.8
  Top Layer w0.12: v1(53.25,45.975) 61.45,45.975 62.975,44.45 65.52,44.45 CN10.6@66.75,45.68
  Bottom Layer w0.12: SB3.1@52.225,45.725 52.475,45.975 v1(53.25,45.975)
NetCN10_34: CN10.34 SB33.1 | length 25.8
  Top Layer w0.12: v1(53.175,5.5) 57.05,5.5 57.925,6.375 v1(62.075,6.375)
  Bottom Layer w0.12: v1(53.175,5.5) 53.175,12.725 53.9,13.45 SB33.1@53.9,14.625 ; v1(62.075,6.375) 62.1,6.4 62.1,7.85 63.15,8.9 65.53,8.9 CN10.34@66.75,10.12
NetJP3_2: JP3.2 R18.1 | length 26.3
  Top Layer w0.12: JP3.2@10.87,48.22 13.175,50.525 v1(18.2,50.525) ; R18.1@16.75,63.425 20.6,63.425 v1(20.625,63.45)
  Bottom Layer w0.12: v1(18.2,50.525) 18.2,52.175 17.9,52.475 17.9,59.65 18.4,60.15 18.4,61.225 v1(20.625,63.45)
NetJP7_2: JP7.2 R31.2 | length 3.6
  Top Layer w0.3: v1(17.2,26.55) 17.205,26.545 R31.2@18.22,26.545
  Bottom Layer w0.3: v1(17.2,26.55) 17.2,25.41 JP7.2@18.22,24.39
NetLD1_2: LD1.2 R3.1 | length 1.5
  Top Layer w0.3: R3.1@59.62,75.515 LD1.2@59.62,77.04
NetLD1_3: LD1.3 R2.1 | length 1.5
  Top Layer w0.3: R2.1@58.12,75.515 LD1.3@58.12,77.04
NetLD2_1: LD2.1 R25.2 | length 1.4
  Top Layer w0.3: LD2.1@36.345,53.39 R25.2@36.345,54.765
NetLD2_2: LD2.2 Q1.3 | length 16.5
  Top Layer w0.12: LD2.2@36.345,51.89 36.345,51.105 v1(36.35,51.1) ; v1(36.35,46.05) 36.725,46.05 37.5,45.275 Q1.3@46.725,45.275
  Bottom Layer w0.12: v1(36.35,46.05) v1(36.35,51.1)
NetLD3_1: LD3.1 R7.1 | length 1.5
  Top Layer w0.3: R7.1@60.2,70.85 LD3.1@61.7,70.85
NetLD4_1: LD4.1 R1.1 | length 1.3
  Top Layer w0.3: LD4.1@47.233,80.38 R1.1@48.533,80.38
NetLD4_2: LD4.2 R6.1 U4.3 | length 7
  Top Layer w0.3: R6.1@45.685,73.97 46.33,73.97 46.705,73.595 U4.3@47.225,73.595 47.233,73.603 LD4.2@47.233,78.88
NetQ1_1: Q1.1 R28.2 R29.2 | length 2.8
  Top Layer w0.12: Q1.1@48.925,44.325 R28.2@50.625,44.325 R29.2@50.625,43.25
NetR4_1: R4.1 U5.F15 | length 2.7
  Top Layer w0.12: R4.1@26.325,74.475 26.375,74.475 27.595,73.255 28.095,73.255 U5.F15@28.4,72.95
NetR5_2: R5.2 U5.J15 | length 1.7
  Top Layer w0.2: R5.2@29.875,74.45 29.875,73.948 30.35,73.473 U5.J15@30.35,72.95
NetR14_2: R14.2 U5.C6 | length 3.4
  Top Layer w0.15: 24.225,66.6 24.395,66.77 26.12,66.77 U5.C6@26.45,67.1
  Top Layer w0.3: R14.2@23.625,65.9 23.625,66 24.225,66.6
NetR16_1: R16.1 R19.1 U5.N3 | length 4.2
  Top Layer w0.15: U5.N3@32.95,65.15 33.275,64.825 34.8,64.825 35.175,64.45 R16.1@35.775,64.45
  Top Layer w0.3: R19.1@35.775,63.4 R16.1@35.775,64.45
NetR17_2: R17.2 U5.D6 | length 6.1
  Top Layer w0.15: 24.65,64.125 24.83,64.305 24.83,65.283 25.022,65.475 26.578,65.475 26.77,65.667 26.77,66.77 U5.D6@27.1,67.1
  Top Layer w0.3: R17.2@23.625,63.6 24.125,63.6 24.65,64.125
NetR20_1: R20.1 X1.3 | length 1.2
  Top Layer w0.15: X1.3@29.05,60.2 R20.1@29.05,61.425
NetR20_2: R20.2 U5.G1 | length 1.5
  Top Layer w0.15: R20.2@29.05,62.325 U5.G1@29.05,63.85
NetR21_2: R21.2 U5.L4 | length 4.7
  Top Layer w0.15: U5.L4@31.65,65.8 31.98,65.47 32.48,65.47 32.63,65.32 32.63,64.345 32.795,64.18 33.12,64.18 33.27,64.03 33.27,63.005
  Top Layer w0.3: R21.2@33.2,62.325 33.27,62.395 33.27,63.005
NetR24_2: R24.2 X1.1 | length 1.3
  Top Layer w0.3: X1.1@30.3,58.55 R24.2@31.55,58.55
NetR29_1: R29.1 SB6.2 | length 4.3
  Top Layer w0.12: R29.1@50.625,41.85 v1(52.45,41.85)
  Bottom Layer w0.12: v1(52.45,41.85) 52.45,39.95 SB6.2@52.825,39.575
NetR32_1: R32.1 SB9.2 | length 3
  Top Layer w0.12: R32.1@23.495,26.84 23.495,26.205 23.75,25.95 24.225,25.95 v1(24.25,25.975)
  Bottom Layer w0.12: SB9.2@23.795,27.115 23.795,26.155 23.975,25.975 v1(24.25,25.975)
NetSB24_2: SB24.2 SB25.2 U13.6 | length 7.2
  Top Layer w0.12: U13.6@31.21,18.19 31.21,19.235 31.475,19.5 v1(34.6,19.5)
  Bottom Layer w0.12: v1(34.6,19.5) 35.12,18.98 SB25.2@35.12,18.365 SB24.2@36.47,18.365
NetSB26_2: SB26.2 SB27.2 SB28.2 U13.5 | length 5.8
  Top Layer w0.12: U13.5@30.71,18.19 30.71,19.385 v1(31.05,19.725)
  Bottom Layer w0.12: v1(31.05,19.725) 31.05,18.385 SB28.2@31.07,18.365 31.245,18.19 33.71,18.19
NetSB29_2: SB29.2 SB30.2 U13.4 | length 4.1
  Top Layer w0.12: v1(30.2,19.475) 30.21,19.465 U13.4@30.21,18.19
  Bottom Layer w0.12: SB30.2@28.37,18.365 SB29.2@29.72,18.365 29.71,18.375 29.71,19.24 29.945,19.475 v1(30.2,19.475)
NetSB31_2: SB31.2 SB32.2 U13.3 | length 6.1
  Top Layer w0.12: v1(27.05,19.375) 29.575,19.375 29.71,19.24 U13.3@29.71,18.19
  Bottom Layer w0.12: SB32.2@25.67,18.365 SB31.2@27.02,18.365 27.02,19.345 v1(27.05,19.375)
OSC32_IN: C57.1 SB31.1 X2.1 | length 6.9
  Top Layer w0.12: C57.1@26.795,12.015 X2.1@26.795,13.515 26.795,13.845 27.45,14.5 28.025,14.5 28.4,14.875 28.4,15.525 v1(28.175,15.75)
  Top Layer w0.2: C57.1@26.745,11.965 C57.1@26.795,12.015
  Bottom Layer w0.12: SB31.1@27.02,17.265 27.02,17.065 28.175,15.91 v1(28.175,15.75)
OSC32_OUT: C58.1 SB30.1 X2.2 | length 5.9
  Top Layer w0.12: v1(28.925,15.75) 28.64,15.465 28.64,14.66 29.295,14.005 X2.2@29.295,13.515 29.345,13.465 C58.1@29.345,11.965
  Bottom Layer w0.12: SB30.1@28.37,17.265 28.37,16.305 v1(28.925,15.75)
OSC_IN: C56.2 SB26.1 X3.1 | length 4.3
  Top Layer w0.12: C56.2@32.895,14.265 X3.1@33.97,14.265 34.175,14.47 v1(34.175,16.025)
  Bottom Layer w0.12: SB26.1@33.77,17.265 33.77,16.43 v1(34.175,16.025)
OSC_OUT: C59.2 SB25.1 X3.3 | length 6.1
  Top Layer w0.12: v1(34.8,16.025) 34.8,15.3 35.1,15 35.375,15 35.675,14.7 35.675,13.57 X3.3@35.02,12.915 C59.2@35.02,11.79
  Bottom Layer w0.12: v1(34.8,16.025) 35.15,16.375 35.15,16.975
PA0: CN7.28 CN8.1 SB21.2 U13.12 | length 53.8
  Top Layer w0.12: CN7.28@5.79,17.74 CN8.1@10.87,17.74 v1(14.34,17.74) 15.11,17.74 16.72,16.13 20.22,16.13 v1(20.3,16.05) ; v1(15.1,8.75) 15.515,9.165 31.038,9.165 32.805,10.932 32.805,11.548 31.585,12.768 31.585,14.974 33.531,16.92 33.534,16.92 33.689,17.075 33.85,17.075 34.21,17.435 U13.12@34.21,18.19
  Bottom Layer w0.12: v1(14.34,17.74) 14.34,16.899 15.8,15.439 15.8,9.45 v1(15.1,8.75) ; v1(20.3,16.05) SB21.2@20.3,17.15
PA1: CN7.30 CN8.2 U13.13 | length 44.1
  Top Layer w0.12: CN7.30@5.79,15.2 CN8.2@10.87,15.2 10.895,15.175 v1(13.05,15.175) ; v1(14.15,8.075) 14.998,8.075 15.848,8.925 31.137,8.925 33.045,10.833 33.045,11.647 31.845,12.847 31.845,14.895 33.63,16.68 33.633,16.68 33.788,16.835 34.11,16.835 34.71,17.435 U13.13@34.71,18.19
  Bottom Layer w0.12: v1(13.05,15.175) 13.22,15.005 13.22,13.665 13.385,13.5 13.385,8.84 v1(14.15,8.075)
PA2: SB17.2 SB18.1 U13.14 | length 4.1
  Top Layer w0.12: U13.14@35.21,18.19 35.21,19.79 v1(35.215,19.79)
  Bottom Layer w0.12: SB18.1@33.87,21.04 33.97,20.94 SB17.2@35.22,20.94 35.22,19.795 v1(35.215,19.79)
PA3: SB22.1 SB23.2 U13.17 | length 8.1
  Top Layer w0.12: U13.17@38.36,20.34 40.085,20.34 v1(40.125,20.3)
  Bottom Layer w0.12: SB23.2@37.845,17.165 39.095,17.165 SB22.1@39.195,17.265 39.335,17.125 40.35,17.125 40.875,17.65 40.875,19.55 v1(40.125,20.3)
PA4: CN7.32 CN8.3 U13.18 | length 54.6
  Top Layer w0.12: CN7.32@5.79,12.66 CN8.3@10.87,12.66 v1(14.1,12.66) ; v1(16.3,8.125) 16.62,8.445 41.395,8.445 v1(41.4,8.45) ; U13.18@38.36,20.84 40.54,20.84 v1(40.55,20.85)
  Bottom Layer w0.12: v1(14.1,12.66) 14.1,9.177 15.152,8.125 v1(16.3,8.125) ; v1(40.55,20.85) 41.4,20 v1(41.4,8.45)
PA5: CN5.6 CN10.11 SB6.1 U13.19 | length 57.9
  Top Layer w0.12: U13.19@38.36,21.34 40.835,21.34 42.875,19.3 42.875,18.664 45.739,15.8 v1(50.675,15.8) ; v1(51.15,39.575) 51.159,39.584 CN5.6@59.13,39.584 60.916,39.584 62.44,38.06 CN10.11@64.21,38.06
  Bottom Layer w0.12: v1(50.675,15.8) 50.675,24.425 51.17,24.92 51.17,39.555 v1(51.15,39.575) ; SB6.1@53.925,39.575 59.121,39.575 CN5.6@59.13,39.584
PA6: CN5.5 CN10.13 U13.20 | length 49.3
  Top Layer w0.12: U13.20@38.36,21.84 40.674,21.84 43.115,19.399 43.115,18.763 45.578,16.3 v1(51.15,16.3) ; v1(51.575,36.125) 58.211,36.125 CN5.5@59.13,37.044 61.231,37.044 62.755,35.52 CN10.13@64.21,35.52
  Bottom Layer w0.12: v1(51.15,16.3) 50.975,16.475 50.975,24.05 51.57,24.645 51.57,36.12 v1(51.575,36.125)
PA7: CN5.4 CN10.15 U13.21 | length 46.4
  Top Layer w0.12: U13.21@38.36,22.34 40.514,22.34 43.355,19.499 43.355,18.862 45.442,16.775 v1(52.25,16.775) ; v1(52.25,33.675) 58.301,33.675 CN5.4@59.13,34.504 61.241,34.504 62.765,32.98 CN10.15@64.21,32.98
  Bottom Layer w0.12: v1(52.25,16.775) v1(52.25,33.675)
PA8: CN9.8 CN10.23 U13.42 | length 51.2
  Top Layer w0.12: U13.42@31.71,29.99 v1(31.71,31.3) ; v1(31.71,32.8) 35.91,37 v1(56.875,37) ; v1(56.875,22.825) 59.125,22.825 CN9.8@59.13,22.82 CN10.23@64.21,22.82
  Bottom Layer w0.12: v1(31.71,31.3) v1(31.71,32.8) ; v1(56.875,22.825) v1(56.875,37)
PA9: CN5.1 CN10.21 U13.43 | length 49.2
  Top Layer w0.12: U13.43@31.21,29.99 v1(31.21,31.79) ; v1(31.21,33.325) 35.312,37.427 57.248,37.427 57.25,37.425 v1(57.3,37.425) ; v1(57.3,26.875) 59.121,26.875 CN5.1@59.13,26.884 61.241,26.884 62.765,25.36 CN10.21@64.21,25.36
  Bottom Layer w0.12: v1(31.21,31.79) v1(31.21,33.325) ; v1(57.3,26.875) v1(57.3,37.425)
PA10: CN9.3 CN10.33 U13.44 | length 65.9
  Top Layer w0.12: U13.44@30.71,29.99 v1(30.71,31.3) ; v1(30.71,33.875) 34.687,37.852 57.723,37.852 v1(57.725,37.85) ; CN9.3@59.13,10.12 CN10.33@64.21,10.12
  Bottom Layer w0.12: v1(30.71,31.3) v1(30.71,33.875) ; v1(57.725,37.85) 57.725,11.525 CN9.3@59.13,10.12
PA11: CN10.14 U13.45 | length 40.9
  Top Layer w0.12: U13.45@30.21,29.99 30.21,31.485 31.075,32.35 33.525,32.35 36.864,35.689 61.291,35.689 62.755,34.225 65.455,34.225 CN10.14@66.75,35.52
PA12: CN10.12 U13.46 | length 43.8
  Top Layer w0.12: U13.46@29.71,29.99 29.71,33.685 34.3,38.275 61.1,38.275 62.65,36.725 65.415,36.725 CN10.12@66.75,38.06
PA13: CN7.13 SB40.2 U13.49 | length 33.9
  Top Layer w0.12: CN7.13@3.25,35.52 4.455,36.725 13.423,36.725 16.025,34.123 v1(16.025,34.075) ; v1(15.7,29.2) 15.72,29.18 24.12,29.18 25.46,27.84 U13.49@26.56,27.84
  Bottom Layer w0.12: v1(15.7,29.2) 15.7,30.3 16.025,30.625 v1(16.025,34.075) 16.8,34.075 17.675,34.95 SB40.2@17.675,35.925 SB40.2@17.65,35.95
PA14: CN7.15 SB41.2 U13.50 | length 32.7
  Top Layer w0.12: CN7.15@3.25,32.98 4.455,34.185 11.7,34.185 12.56,33.325 15.957,33.325 16.912,34.28 17.707,34.28 18.432,35.005 21.83,35.005 v1(22.225,35.4) ; v1(24.85,27.7) 25.21,27.34 U13.50@26.56,27.34
  Bottom Layer w0.12: SB41.2@23.175,35.925 22.45,35.925 22.225,35.7 v1(22.225,35.4) 22.225,31.785 24.65,29.36 24.65,27.9 v1(24.85,27.7)
PA15: R32.2 SB7.1 SB37.2 U13.51 | length 32.7
  Top Layer w0.12: v1(22.225,26.025) 22.225,26.85 22.925,27.55 24.175,27.55 24.395,27.33 R32.2@24.395,26.84 U13.51@26.56,26.84
  Bottom Layer w0.12: SB37.2@21.25,3.95 21.845,3.95 22.02,4.125 22.02,6.193 22.185,6.358 22.185,11.126 20.98,12.331 20.98,13.592 19.31,15.262 19.31,19.074 19.826,19.59 20.318,19.59 22.225,21.497 v1(22.225,26.025) SB7.1@22.225,27.225
PB0: CN7.34 CN8.4 U13.24 | length 56.2
  Top Layer w0.12: CN7.34@5.79,10.12 CN8.4@10.87,10.12 13.745,7.245 19.381,7.245 20.341,8.205 40.625,8.205 40.905,7.925 v1(41.825,7.925) ; U13.24@38.36,23.84 v1(40.285,23.84)
  Bottom Layer w0.12: v1(40.285,23.84) 40.285,22.027 41.825,20.487 v1(41.825,7.925)
PB1: CN10.24 U13.25 | length 35.8
  Top Layer w0.12: U13.25@38.36,24.34 40.358,24.34 40.725,23.973 40.725,23.147 44.11,19.762 44.11,19.126 45.161,18.075 v1(53.3,18.075) ; v1(53.3,21.5) 65.43,21.5 CN10.24@66.75,22.82
  Bottom Layer w0.12: v1(53.3,18.075) v1(53.3,21.5)
PB2: CN10.22 U13.26 | length 38
  Top Layer w0.12: U13.26@38.36,24.84 40.197,24.84 40.965,24.072 40.965,23.246 44.35,19.861 44.35,19.225 45.075,18.5 v1(54.725,18.5) ; v1(54.725,24.075) 65.465,24.075 CN10.22@66.75,25.36
  Bottom Layer w0.12: v1(54.725,18.5) v1(54.725,24.075)
PB3: CN9.4 CN10.31 SB15.1 U13.56 | length 72.3
  Top Layer w0.12: v1(23.275,6.45) v1(56.775,6.45) ; U13.56@26.56,24.34 27.79,24.34 v1(27.8,24.35) ; v1(56.775,12.65) 56.785,12.66 CN9.4@59.13,12.66 CN10.31@64.21,12.66
  Bottom Layer w0.12: v1(23.275,6.45) 23.275,7.3 23.125,7.45 23.125,11.204 21.7,12.629 21.7,19.275 22.305,19.88 26.005,19.88 26.645,20.52 SB15.1@26.645,24.34 27.79,24.34 v1(27.8,24.35) ; v1(56.775,6.45) v1(56.775,12.65)
PB4: CN9.6 CN10.27 U13.57 | length 76.2
  Top Layer w0.12: v1(22.425,6.025) v1(56.25,6.025) ; v1(24.45,23.425) 24.865,23.84 U13.57@26.56,23.84 ; v1(56.25,17.75) 59.12,17.75 CN9.6@59.13,17.74 CN10.27@64.21,17.74
  Bottom Layer w0.12: v1(22.425,6.025) 22.425,11.225 21.22,12.43 21.22,19.474 22.106,20.36 24.125,20.36 24.45,20.685 v1(24.45,23.425) ; v1(56.25,6.025) v1(56.25,17.75)
PB5: CN9.5 CN10.29 U13.58 | length 71
  Top Layer w0.12: v1(22.85,6.875) v1(57.35,6.875) ; v1(24.9,22.925) 25.315,23.34 U13.58@26.56,23.34 ; v1(57.3,15.2) CN9.5@59.13,15.2 CN10.29@64.21,15.2
  Bottom Layer w0.12: v1(22.85,6.875) 22.885,6.91 22.885,11.104 21.46,12.529 21.46,19.374 22.206,20.12 24.495,20.12 24.9,20.525 v1(24.9,22.925) ; v1(57.3,15.2) 57.3,6.925 v1(57.35,6.875)
PB6: CN5.3 CN10.17 U13.59 | length 45.6
  Top Layer w0.12: U13.59@26.56,22.84 29.315,22.84 31.125,24.65 31.125,27.525 31.9,28.3 36.2,28.3 36.8,28.9 36.8,31.45 37.8,32.45 54.175,32.45 54.661,31.964 CN5.3@59.13,31.964 61.241,31.964 62.765,30.44 CN10.17@64.21,30.44
PB7: CN7.21 U13.60 | length 26
  Top Layer w0.12: CN7.21@3.25,25.36 4.455,26.565 14.76,26.565 15.75,25.575 18.875,25.575 20.09,24.36 23.49,24.36 24.045,23.805 24.045,23.092 24.797,22.34 U13.60@26.56,22.34
PB8: JP7.1 SB2.2 SB4.1 U13.61 | length 86.3
  Top Layer w0.12: v1(12.6,21.925) 18.145,21.925 18.23,21.84 19.825,21.84 20.215,21.45 21.35,21.45 21.74,21.84 U13.61@26.56,21.84 ; v1(14.15,49.15) 14.8,49.15 15.41,49.76 50.96,49.76 v1(51.325,50.125)
  Bottom Layer w0.12: v1(12.6,21.925) 12.95,22.275 12.95,31.554 13.565,32.169 13.565,35.279 13.966,35.68 15.978,35.68 16.265,35.967 16.265,39.402 15.69,39.977 15.69,41.56 15.275,41.975 SB4.1@15.275,43.3 16.225,43.3 16.77,43.845 16.77,45.531 14.435,47.866 14.435,48.865 v1(14.15,49.15) ; v1(51.325,50.125) 51.7,49.75 SB2.2@52.975,49.75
